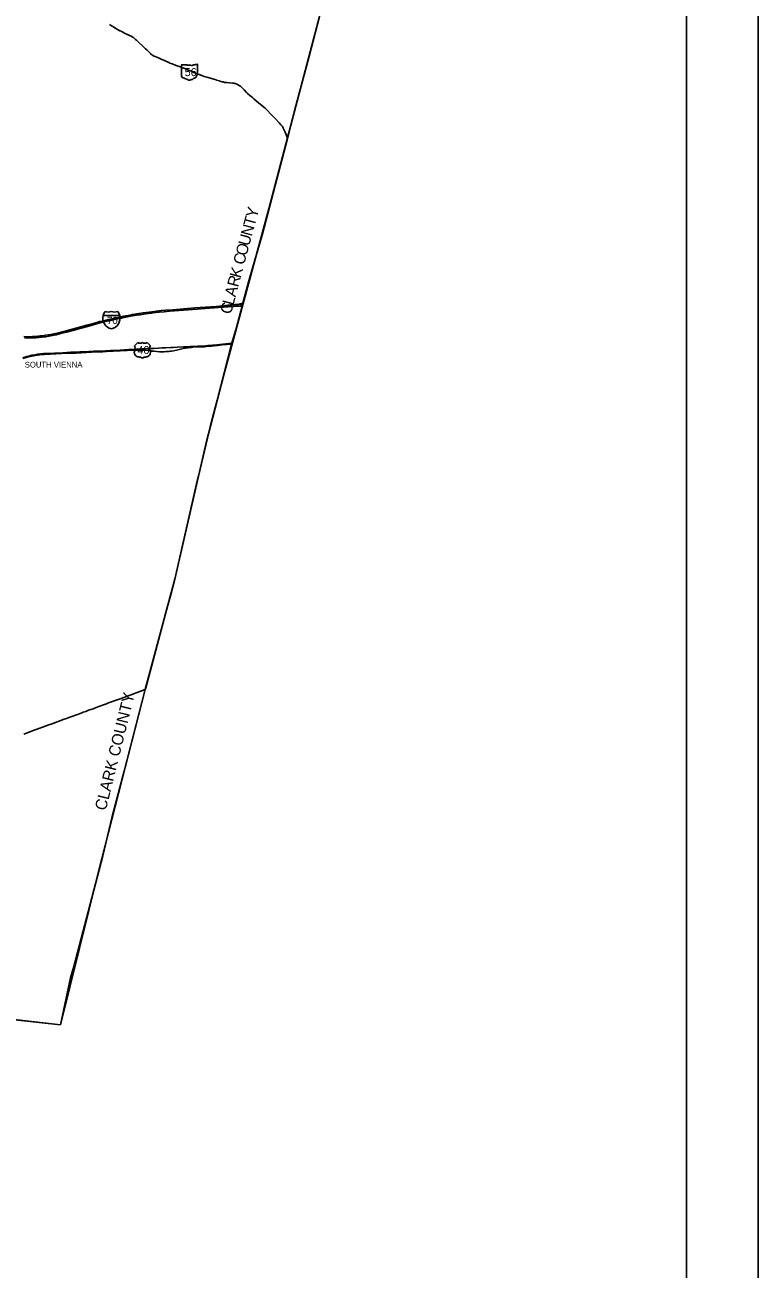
# Model space of a CAD drawing. Extents: x 0 to 34, y 0 to 22.
# Drawn here: x 7.975 to 9, y 14.836 to 16.576 of the extents above; entities that cross this region are included whole.
import ezdxf

# ---------------------------------------------------------------- set-up
doc = ezdxf.new("R2010")
doc.units = 0
for name, color, linetype in [('GM_X_Corporation_Text', 7, 'Continuous'), ('GM_X_County', 7, 'Continuous'), ('GM_X_County_Text', 7, 'Continuous'), ('GM_X_Interchange_Ramps', 7, 'Continuous'), ('GM_X_Interstate_Location', 7, 'Continuous'), ('GM_X_Interstate_Route', 7, 'Continuous'), ('GM_X_Interstate_Shield', 7, 'Continuous'), ('GM_X_State_Location', 7, 'Continuous'), ('GM_X_State_Route', 7, 'Continuous'), ('GM_X_State_Shield', 7, 'Continuous'), ('GM_X_US_Location', 7, 'Continuous'), ('GM_X_US_Route', 7, 'Continuous'), ('GM_X_US_Shield', 7, 'Continuous'), ('SC_Scratch1', 7, 'Continuous'), ('SH_Data', 7, 'Continuous')]:
    doc.layers.add(name, color=color, linetype=linetype)

msp = doc.modelspace()

# ---------------------------------------------------------------- linework, layer by layer
at = {"layer": 'GM_X_County'}
msp.add_lwpolyline([(8.3874, 16.5894), (8.3721, 16.5303), (8.3527, 16.4572), (8.3424, 16.4167), (8.3072, 16.2837), (8.2885, 16.2177), (8.2801, 16.1864), (8.2797, 16.1851), (8.2792, 16.1831), (8.279, 16.1824), (8.2709, 16.1523), (8.2645, 16.1305), (8.2642, 16.1294), (8.2442, 16.0508), (8.2346, 16.0156), (8.2202, 15.9546), (8.2179, 15.9446), (8.2168, 15.9401), (8.185, 15.8007), (8.1788, 15.7772), (8.1743, 15.7607), (8.1442, 15.6487), (8.1436, 15.6462), (8.114, 15.532), (8.1082, 15.5091), (8.097, 15.4669), (8.0841, 15.4137), (8.0436, 15.2588), (8.0393, 15.2428), (8.025, 15.1773), (7.9267, 15.1881)], dxfattribs=at)
at = {"layer": 'GM_X_Interchange_Ramps'}
for points in [[(8.2801, 16.1864), (8.2769, 16.1857), (8.2763, 16.1856), (8.2749, 16.1853), (8.2621, 16.184), (8.2523, 16.183), (8.2516, 16.1828)], [(8.2668, 16.1821), (8.2673, 16.182), (8.2696, 16.1822), (8.2715, 16.1823), (8.273, 16.1824), (8.2742, 16.1825), (8.2753, 16.1825), (8.2766, 16.1825), (8.2785, 16.1824), (8.279, 16.1824)]]:
    msp.add_lwpolyline(points, dxfattribs=at)
at = {"layer": 'GM_X_Interstate_Route'}
msp.add_line((8.279, 16.1831), (8.2792, 16.1831), dxfattribs=at)
for points in [[(8.2516, 16.1828), (8.2608, 16.1835), (8.2631, 16.1837), (8.2683, 16.1841), (8.2797, 16.185)], [(7.974, 16.1398), (7.9766, 16.1397), (7.9821, 16.1397), (7.9861, 16.1399), (7.9879, 16.14), (7.9905, 16.1401), (7.9936, 16.1403), (7.9956, 16.1405), (7.9971, 16.1407), (7.9998, 16.141), (8.0022, 16.1413), (8.0042, 16.1416), (8.0078, 16.1421), (8.0097, 16.1424), (8.0136, 16.1431), (8.018, 16.144), (8.0225, 16.1451), (8.0236, 16.1453), (8.0258, 16.1459), (8.0274, 16.1464), (8.0332, 16.1479), (8.0484, 16.152), (8.0585, 16.1548), (8.0614, 16.1556), (8.0682, 16.1574), (8.0728, 16.1587), (8.0758, 16.1595), (8.0803, 16.1607), (8.0836, 16.1616), (8.0929, 16.1639), (8.0972, 16.1648), (8.1009, 16.1657), (8.1032, 16.1662), (8.1056, 16.1667), (8.1092, 16.1674), (8.1112, 16.1678), (8.1133, 16.1682), (8.1165, 16.1689), (8.1171, 16.169), (8.1198, 16.1695), (8.1221, 16.1699), (8.1228, 16.17), (8.1256, 16.1705), (8.129, 16.1711), (8.1318, 16.1716), (8.1407, 16.173), (8.1492, 16.1742), (8.1529, 16.1746), (8.1563, 16.175), (8.1588, 16.1753), (8.1659, 16.1761), (8.1722, 16.1767), (8.1822, 16.1774), (8.213, 16.1798), (8.2429, 16.1821), (8.2474, 16.1825), (8.2516, 16.1828)], [(8.112, 16.1661), (8.1186, 16.1674), (8.1227, 16.1682), (8.1228, 16.1682), (8.1285, 16.1692), (8.1312, 16.1696)], [(8.1312, 16.1696), (8.1358, 16.1704), (8.1363, 16.1704), (8.1444, 16.1717), (8.1479, 16.1722), (8.1503, 16.1725), (8.1522, 16.1727), (8.1547, 16.173), (8.1582, 16.1734), (8.163, 16.1739), (8.17, 16.1746), (8.1779, 16.1753), (8.1908, 16.1763), (8.216, 16.1782), (8.2273, 16.1791), (8.246, 16.1805)], [(8.246, 16.1805), (8.2665, 16.1821), (8.2668, 16.1821)], [(8.2668, 16.1821), (8.2767, 16.1829), (8.279, 16.1831)], [(7.9747, 16.138), (7.9763, 16.1379), (7.978, 16.1379), (7.9795, 16.1379), (7.9812, 16.1379), (7.9837, 16.138), (7.9906, 16.1383), (7.9948, 16.1386), (7.9974, 16.1388), (7.9995, 16.1391), (8.0018, 16.1393), (8.0045, 16.1397), (8.0089, 16.1404), (8.0138, 16.1413), (8.019, 16.1423), (8.0221, 16.143), (8.0289, 16.1449), (8.0337, 16.1461), (8.0424, 16.1485), (8.0541, 16.1517), (8.0629, 16.1541), (8.0678, 16.1554), (8.0724, 16.1567), (8.0806, 16.1589), (8.088, 16.1608), (8.0949, 16.1624), (8.1019, 16.164), (8.1104, 16.1658), (8.112, 16.1661)]]:
    msp.add_lwpolyline(points, dxfattribs=at)
at = {"layer": 'GM_X_Interstate_Shield'}
for p, q in [((8.0846, 16.1692), (8.1078, 16.1692)), ((8.1078, 16.1692), (8.0846, 16.1692)), ((8.1078, 16.1692), (8.0846, 16.1692))]:
    msp.add_line(p, q, dxfattribs=at)
for centre, start, end in [((8.0993, 16.1655), 165.8066, 258.463), ((8.0993, 16.1655), 141.669, 165.8066), ((8.0918, 16.1893), 253.0091, 286.9909), ((8.1006, 16.1893), 253.0091, 286.9909), ((8.0932, 16.1655), 281.537, 14.1934), ((8.0932, 16.1655), 14.1934, 38.331)]:
    msp.add_arc(centre, 0.0151, start, end, dxfattribs=at)
at = {"layer": 'GM_X_State_Route'}
msp.add_lwpolyline([(8.0938, 16.5763), (8.0951, 16.5754), (8.0971, 16.5742), (8.1004, 16.5721), (8.1026, 16.5708), (8.1058, 16.569), (8.1082, 16.5676), (8.1098, 16.5668), (8.1112, 16.5661), (8.1157, 16.5638), (8.1207, 16.5613), (8.1247, 16.5593), (8.1255, 16.5589), (8.1261, 16.5586), (8.1267, 16.5582), (8.1272, 16.5579), (8.1277, 16.5575), (8.1282, 16.5571), (8.1301, 16.5555), (8.1312, 16.5546), (8.1328, 16.5531), (8.1347, 16.5512), (8.1401, 16.5461), (8.1435, 16.5429), (8.144, 16.5424), (8.1457, 16.5407), (8.148, 16.5384), (8.1507, 16.5356), (8.1514, 16.535), (8.1519, 16.5345), (8.1523, 16.5342), (8.1527, 16.5339), (8.1533, 16.5335), (8.1538, 16.5332), (8.1544, 16.5328), (8.1548, 16.5326), (8.1561, 16.5321), (8.1576, 16.5314), (8.162, 16.5295), (8.1656, 16.5279), (8.1714, 16.5254), (8.1764, 16.523), (8.1779, 16.5224), (8.1812, 16.5212), (8.1823, 16.5208), (8.188, 16.5187), (8.1922, 16.5171), (8.1974, 16.5151), (8.2001, 16.5141), (8.2028, 16.5131), (8.2052, 16.5121), (8.2081, 16.5108), (8.2125, 16.5089), (8.2147, 16.508), (8.2201, 16.506), (8.2236, 16.5047), (8.226, 16.5038), (8.2296, 16.5028), (8.2346, 16.5013), (8.2392, 16.4999), (8.2429, 16.4987), (8.2432, 16.4986), (8.2472, 16.4973), (8.2479, 16.4971), (8.251, 16.4962), (8.2523, 16.4959), (8.2536, 16.4956), (8.2543, 16.4954), (8.2551, 16.4953), (8.2575, 16.495), (8.2611, 16.4947), (8.2653, 16.4943), (8.2677, 16.4941), (8.2683, 16.494), (8.2687, 16.4939), (8.2692, 16.4938), (8.2698, 16.4936), (8.2703, 16.4934), (8.2708, 16.4933), (8.2713, 16.493), (8.2717, 16.4928), (8.2734, 16.4919), (8.2754, 16.4907), (8.2765, 16.4899), (8.2766, 16.4899), (8.2775, 16.4891), (8.2786, 16.488), (8.2817, 16.4848), (8.2852, 16.4811), (8.2865, 16.4798), (8.2897, 16.4771), (8.2933, 16.474), (8.2955, 16.4722), (8.3024, 16.4664), (8.3061, 16.4634), (8.3095, 16.4606), (8.3116, 16.4589), (8.3118, 16.4586), (8.3121, 16.4584), (8.3127, 16.4578), (8.314, 16.4565), (8.3191, 16.4508), (8.3219, 16.4479), (8.3254, 16.4444), (8.3307, 16.4389), (8.3332, 16.4362), (8.3342, 16.435), (8.3348, 16.4343), (8.3351, 16.4341), (8.3352, 16.4339), (8.3354, 16.4335), (8.3358, 16.4329), (8.3365, 16.4314), (8.3389, 16.4258), (8.3408, 16.4212), (8.3417, 16.4187), (8.3422, 16.4174), (8.3424, 16.4166)], dxfattribs=at)
at = {"layer": 'GM_X_State_Shield'}
for p, q in [((8.1943, 16.5199), (8.1943, 16.5029)), ((8.2011, 16.5201), (8.1946, 16.5201)), ((8.2167, 16.5117), (8.2167, 16.5206)), ((8.2167, 16.5117), (8.2167, 16.5117))]:
    msp.add_line(p, q, dxfattribs=at)
for centre, radius, start, end in [((8.1946, 16.5199), 0.000259, 98.1301, 188.1301), ((8.2027, 16.5221), 0.00251, 231.6195, 271.1119), ((8.2035, 16.5106), 0.00903, 80.4867, 94.9883), ((8.2056, 16.52), 0.000725, 219.7921, 297.1024), ((8.2066, 16.518), 0.00151, 54.4667, 119.1411), ((8.2086, 16.5207), 0.00181, 233.8562, 294.8282), ((8.2118, 16.515), 0.00477, 97.3462, 120.7689), ((8.2088, 16.5433), 0.0237, 275.8445, 288.9065), ((8.2165, 16.5206), 0.000249, 351.8621, 97.738), ((8.1946, 16.5028), 0.000262, 171.9584, 258.3066), ((8.1946, 16.5046), 0.002, 267.339, 280.6039), ((8.1951, 16.5019), 0.00072, 29.7484, 93.2717), ((8.2041, 16.5172), 0.0171, 240.4129, 257.1985), ((8.199, 16.4952), 0.00536, 47.1842, 75.836), ((8.2048, 16.5018), 0.0034, 230.7004, 286.2918), ((8.2068, 16.4959), 0.0028, 85.6951, 111.2099), ((8.207, 16.5005), 0.00181, 268.777, 315.5493), ((8.2087, 16.4989), 0.00051, 65.7517, 132.6484), ((8.2085, 16.5012), 0.00192, 282.8732, 323.2771), ((8.2126, 16.4981), 0.00325, 94.4031, 142.5768), ((8.2101, 16.5068), 0.00594, 292.3089, 8.9858), ((8.2176, 16.508), 0.00168, 136.8065, 186.9296), ((8.2167, 16.511), 0.000386, 107.944, 210.337), ((8.2142, 16.5099), 0.00231, 340.033, 23.6496), ((8.2165, 16.5116), 0.000267, 289.6038, 7.7341)]:
    msp.add_arc(centre, radius, start, end, dxfattribs=at)
at = {"layer": 'GM_X_US_Route'}
msp.add_line((8.2076, 16.1246), (8.2081, 16.1247), dxfattribs=at)
for points in [[(7.9805, 16.1126), (7.9821, 16.113), (7.9852, 16.1137), (7.9893, 16.1145), (7.9932, 16.1151), (7.9944, 16.1152), (7.9956, 16.1154), (7.9976, 16.1156), (7.9995, 16.1158), (8.0016, 16.116), (8.004, 16.1161), (8.0169, 16.1167), (8.0282, 16.1172), (8.0398, 16.1178), (8.041, 16.1178), (8.0445, 16.118), (8.0522, 16.1184), (8.0569, 16.1186), (8.0645, 16.1189), (8.0719, 16.1193), (8.079, 16.1196), (8.088, 16.12), (8.0951, 16.1203), (8.1085, 16.121), (8.1206, 16.1216), (8.1288, 16.122), (8.1301, 16.1221)], [(7.9926, 16.114), (7.9933, 16.1141), (7.9946, 16.1142), (7.9963, 16.1144), (7.9984, 16.1146), (8.0021, 16.1149), (8.0106, 16.1154), (8.0187, 16.1157), (8.0264, 16.116), (8.038, 16.1165), (8.041, 16.1166), (8.0467, 16.1168), (8.0759, 16.1183), (8.0841, 16.1187), (8.0896, 16.1189), (8.0986, 16.1193), (8.1083, 16.1197), (8.1183, 16.1202), (8.1291, 16.1207), (8.1349, 16.1209), (8.1376, 16.1209), (8.1388, 16.1209)], [(8.1301, 16.1221), (8.1385, 16.1225), (8.149, 16.123), (8.1508, 16.1231), (8.1556, 16.1233), (8.162, 16.1236), (8.1673, 16.1239), (8.1719, 16.1241), (8.1793, 16.1245), (8.1827, 16.1246), (8.1882, 16.1249), (8.1972, 16.1253), (8.2057, 16.1257)], [(8.1388, 16.1209), (8.1405, 16.1208), (8.1406, 16.1208)], [(8.1406, 16.1208), (8.1419, 16.1208), (8.1433, 16.1207), (8.1444, 16.1206), (8.1478, 16.1202), (8.1512, 16.1198), (8.1517, 16.1198), (8.1528, 16.1196), (8.1559, 16.1192), (8.1596, 16.1189), (8.1636, 16.1187), (8.1662, 16.1186), (8.1676, 16.1186), (8.1699, 16.1187), (8.1725, 16.1188), (8.1747, 16.119), (8.1765, 16.1191), (8.1784, 16.1194), (8.1801, 16.1196), (8.183, 16.1201), (8.189, 16.1213), (8.1892, 16.1214), (8.1964, 16.123), (8.1997, 16.1236), (8.2034, 16.1242), (8.2063, 16.1245), (8.2076, 16.1246)], [(8.2057, 16.1257), (8.2067, 16.1258), (8.2135, 16.1261), (8.2166, 16.1262), (8.2204, 16.1264), (8.2243, 16.1266), (8.2278, 16.127), (8.2309, 16.1272), (8.2435, 16.1284), (8.2645, 16.1305)], [(8.2081, 16.1247), (8.21, 16.1248), (8.2208, 16.1253), (8.224, 16.1255), (8.2265, 16.1257), (8.2287, 16.1259), (8.236, 16.1266), (8.2449, 16.1275), (8.251, 16.1281), (8.2642, 16.1294)], [(7.9724, 16.1103), (7.9783, 16.112), (7.9805, 16.1126)], [(7.9724, 16.1092), (7.9726, 16.1093), (7.9772, 16.1106), (7.9805, 16.1115), (7.9807, 16.1115)], [(7.9807, 16.1115), (7.9846, 16.1125), (7.9877, 16.1131), (7.9919, 16.1138), (7.9926, 16.114)], [(7.9739, 15.5838), (7.9791, 15.5858), (7.987, 15.5887), (7.9912, 15.5902), (8.0051, 15.5953), (8.0088, 15.5967), (8.0135, 15.5984), (8.0169, 15.5997), (8.0221, 15.6016), (8.0304, 15.6046), (8.0333, 15.6057), (8.038, 15.6074), (8.0501, 15.6119), (8.055, 15.6137), (8.057, 15.6144), (8.0605, 15.6157), (8.0644, 15.6172), (8.0706, 15.6194), (8.0749, 15.621), (8.0852, 15.6248), (8.0894, 15.6264), (8.0924, 15.6275), (8.0964, 15.6289), (8.1013, 15.6307), (8.1097, 15.6338), (8.1172, 15.6365), (8.1211, 15.638), (8.1241, 15.639), (8.1273, 15.6402), (8.1325, 15.6421), (8.1362, 15.6435), (8.1436, 15.6461)]]:
    msp.add_lwpolyline(points, dxfattribs=at)
at = {"layer": 'GM_X_US_Shield'}
for p, q in [((8.133, 16.1317), (8.1284, 16.1271)), ((8.1508, 16.1271), (8.1461, 16.1317)), ((8.1349, 16.1112), (8.1358, 16.1112)), ((8.1433, 16.1112), (8.1442, 16.1112))]:
    msp.add_line(p, q, dxfattribs=at)
for centre, radius, start, end in [((8.1363, 16.1351), 0.00466, 225.573, 314.427), ((8.1428, 16.1351), 0.00466, 225.573, 314.427), ((8.1348, 16.1178), 0.00653, 154.8319, 270.6383), ((8.123, 16.1233), 0.00653, 334.5471, 35.0009), ((8.1443, 16.1178), 0.00653, 269.3617, 25.1681), ((8.1561, 16.1233), 0.00653, 144.9991, 205.4529), ((8.1358, 16.1066), 0.00466, 36.8699, 90), ((8.1433, 16.1066), 0.00466, 90, 143.1301)]:
    msp.add_arc(centre, radius, start, end, dxfattribs=at)
at = {"layer": 'SC_Scratch1'}
msp.add_lwpolyline([(8.3874, 16.5894), (8.3472, 16.4357), (8.3164, 16.3185), (8.2532, 16.0862), (8.2288, 15.9913), (8.185, 15.8007), (8.1436, 15.6461), (8.0783, 15.3916), (8.025, 15.1773), (7.7582, 15.2079), (7.7597, 15.2198), (7.7281, 15.2228), (7.4833, 15.2492), (7.3478, 15.2619), (7.3403, 15.3071), (7.2249, 15.323), (6.9858, 15.3578), (6.9402, 15.3643), (6.9529, 15.5105), (6.8443, 15.521), (6.4741, 15.5517)], dxfattribs=at)
at = {"layer": 'SH_Data'}
for p, q in [((9, 21), (9, 14)), ((8.9, 20.9), (8.9, 14.1))]:
    msp.add_line(p, q, dxfattribs=at)

# ---------------------------------------------------------------- texts
at = {"layer": 'GM_X_Corporation_Text'}
msp.add_text('SOUTH VIENNA', height=0.008037, rotation=0, dxfattribs=at).set_placement((7.9752, 16.0965))
at = {"layer": 'GM_X_County_Text'}
for s, height, rotation, p in [('T', 0.0161, 74.9663, (8.2961, 16.2929)), ('Y', 0.0161, 74.9663, (8.2992, 16.3045)), ('N', 0.0161, 74.9644, (8.2924, 16.2792)), ('U', 0.0161, 74.9655, (8.2887, 16.2655)), ('C', 0.0161, 74.9689, (8.2816, 16.2392)), ('O', 0.0161, 74.9655, (8.285, 16.2518)), ('K', 0.0161, 75.0523, (8.2767, 16.2207)), ('R', 0.0161, 75.1423, (8.2733, 16.2081)), ('A', 0.0161, 75.2271, (8.2697, 16.1943)), ('C', 0.0161, 75.2473, (8.2633, 16.1701)), ('L', 0.0161, 75.2476, (8.2667, 16.1827)), ('CLARK COUNTY', 0.016074, 76.0406, (8.0884, 15.476))]:
    msp.add_text(s, height=height, rotation=rotation, dxfattribs=at).set_placement(p)
at = {"layer": 'GM_X_Interstate_Location'}
msp.add_text('70', height=0.0000161, rotation=0, dxfattribs=at).set_placement((8.093, 16.1595))
for s in ['.', '-', ',']:
    msp.add_text(s, height=0.0000161, dxfattribs=at).set_placement((8.0962, 16.1628))
at = {"layer": 'GM_X_Interstate_Shield'}
msp.add_text('70', height=0.01005, dxfattribs=at).set_placement((8.0901, 16.1575))
at = {"layer": 'GM_X_State_Location'}
msp.add_text('56', height=0.0000161, rotation=0, dxfattribs=at).set_placement((8.2012, 16.5091))
for s in ['s', 'r']:
    msp.add_text(s, height=0.0000161, dxfattribs=at).set_placement((8.2053, 16.5102))
at = {"layer": 'GM_X_State_Shield'}
msp.add_text('56', height=0.01119, dxfattribs=at).set_placement((8.1987, 16.5041))
at = {"layer": 'GM_X_US_Location'}
msp.add_text('40', height=0.0000161, rotation=0, dxfattribs=at).set_placement((8.1362, 16.1176))
for s in ['0', '/']:
    msp.add_text(s, height=0.0000161, dxfattribs=at).set_placement((8.1396, 16.1209))
at = {"layer": 'GM_X_US_Shield'}
msp.add_text('40', height=0.01119, dxfattribs=at).set_placement((8.1327, 16.1154))

doc.saveas('drawing.dxf')
